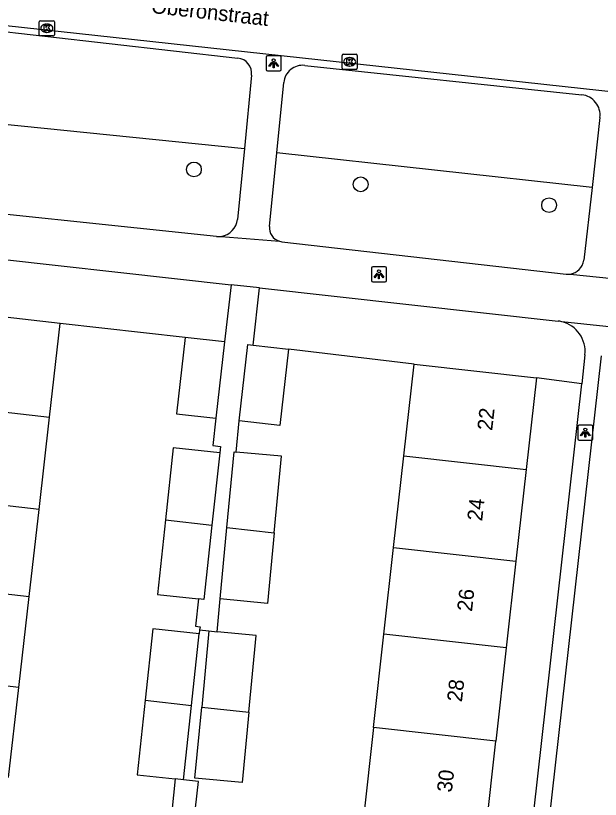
# Model space of a CAD drawing. Extents: x 161928 to 163055, y 386475 to 387428.
# Drawn here: x 162177.9 to 162216.7, y 386884.8 to 386936.8 of the extents above; entities that cross this region are included whole.
import ezdxf

# ---------------------------------------------------------------- set-up
doc = ezdxf.new("R2010")
doc.units = 0
for name, color, linetype in [('IMGEO_Boom', 7, 'Continuous'), ('IMGEO_Erf', 7, 'Continuous'), ('IMGEO_Groenvoorziening', 7, 'Continuous'), ('IMGEO_Kolk', 7, 'Continuous'), ('IMGEO_Lichtpunt', 7, 'Continuous'), ('IMGEO_Openbare_ruimte_label', 7, 'Continuous'), ('IMGEO_Pand', 7, 'Continuous'), ('IMGEO_Pand_nummerreeks', 7, 'Continuous'), ('IMGEO_Rijbaan_lokaal_open', 7, 'Continuous'), ('IMGEO_Voetpad_open', 7, 'Continuous')]:
    doc.layers.add(name, color=color, linetype=linetype)

msp = doc.modelspace()

# ---------------------------------------------------------------- linework, layer by layer
at = {"layer": 'IMGEO_Boom'}
for centre in [(162189.755, 386926.564), (162200.806, 386925.576), (162213.295, 386924.199)]:
    msp.add_circle(centre, 0.489, dxfattribs=at)
at = {"layer": 'IMGEO_Erf'}
msp.add_lwpolyline([(162190.133, 386896.057), (162190.105, 386895.794)], dxfattribs=at)
at = {"layer": 'IMGEO_Groenvoorziening'}
for points in [[(162169.363, 386930.364), (162193.098, 386927.955)], [(162216.138, 386925.375), (162195.245, 386927.667)], [(162189.178, 386915.439), (162180.893, 386916.367)], [(162204.343, 386913.676), (162196.021, 386914.657)], [(162215.453, 386912.353), (162212.452, 386912.769)]]:
    msp.add_lwpolyline(points, dxfattribs=at)
at = {"layer": 'IMGEO_Kolk'}
for p, q in [((162179.503, 386935.493), (162179.503, 386936.345)), ((162179.578, 386936.419), (162180.43, 386936.419)), ((162180.504, 386936.345), (162180.504, 386935.493)), ((162179.991, 386936.199), (162180.016, 386936.199)), ((162180.43, 386935.419), (162179.578, 386935.419)), ((162180.014, 386935.639), (162179.989, 386935.639)), ((162199.648, 386934.197), (162200.5, 386934.197)), ((162199.573, 386933.271), (162199.573, 386934.123)), ((162200.061, 386933.977), (162200.086, 386933.977)), ((162200.574, 386934.123), (162200.574, 386933.271)), ((162200.5, 386933.197), (162199.648, 386933.197)), ((162200.084, 386933.417), (162200.059, 386933.417))]:
    msp.add_line(p, q, dxfattribs=at)
for points in [[(162179.503, 386935.493), (162179.503, 386936.345)], [(162179.578, 386936.419), (162180.43, 386936.419)], [(162180.504, 386936.345), (162180.504, 386935.493)], [(162179.824, 386936.119), (162179.947, 386936.119), (162179.947, 386935.968), (162180.077, 386936.119), (162180.241, 386936.119), (162180.095, 386935.968), (162180.248, 386935.719), (162180.096, 386935.719), (162180.011, 386935.883), (162179.947, 386935.816), (162179.947, 386935.719), (162179.824, 386935.719), (162179.824, 386936.119)], [(162180.43, 386935.419), (162179.578, 386935.419)], [(162199.648, 386934.197), (162200.5, 386934.197)], [(162199.573, 386933.271), (162199.573, 386934.123)], [(162199.894, 386933.897), (162200.017, 386933.897), (162200.017, 386933.746), (162200.147, 386933.897), (162200.311, 386933.897), (162200.165, 386933.746), (162200.318, 386933.497), (162200.166, 386933.497), (162200.081, 386933.661), (162200.017, 386933.594), (162200.017, 386933.497), (162199.894, 386933.497), (162199.894, 386933.897)], [(162200.574, 386934.123), (162200.574, 386933.271)], [(162200.5, 386933.197), (162199.648, 386933.197)]]:
    msp.add_lwpolyline(points, dxfattribs=at)
for centre, start, end in [((162179.58, 386936.343), 91.552, 178.448), ((162179.58, 386936.343), 91.552, 178.448), ((162180.428, 386936.343), 1.552, 88.448), ((162180.428, 386936.343), 1.552, 88.448), ((162179.58, 386935.495), 181.552, 268.448), ((162179.58, 386935.495), 181.552, 268.448), ((162180.428, 386935.495), 271.552, 358.448), ((162180.428, 386935.495), 271.552, 358.448), ((162199.65, 386934.121), 91.552, 178.448), ((162199.65, 386934.121), 91.552, 178.448), ((162200.498, 386934.121), 1.552, 88.448), ((162200.498, 386934.121), 1.552, 88.448), ((162199.65, 386933.273), 181.552, 268.448), ((162199.65, 386933.273), 181.552, 268.448), ((162200.498, 386933.273), 271.552, 358.448), ((162200.498, 386933.273), 271.552, 358.448)]:
    msp.add_arc(centre, 0.0765, start, end, dxfattribs=at)
for centre, major_axis, ratio, start_param, end_param in [((162179.99, 386935.919), (-0.387, 0.002), 0.722429, 4.712389, 7.853982), ((162180.015, 386935.919), (-0.39, 0.002), 0.717154, 1.570796, 4.712389), ((162200.06, 386933.697), (-0.387, 0.002), 0.722429, 4.712389, 7.853982), ((162200.085, 386933.697), (-0.39, 0.002), 0.717154, 1.570796, 4.712389)]:
    msp.add_ellipse(centre, major_axis=major_axis, ratio=ratio, start_param=start_param, end_param=end_param, dxfattribs=at)
at = {"layer": 'IMGEO_Lichtpunt'}
for p, q in [((162194.538, 386934.003), (162194.538, 386933.196)), ((162194.538, 386934.003), (162194.538, 386933.196)), ((162195.44, 386934.098), (162194.632, 386934.098)), ((162195.44, 386934.098), (162194.632, 386934.098)), ((162195.534, 386933.196), (162195.534, 386934.003)), ((162195.534, 386933.196), (162195.534, 386934.003)), ((162194.632, 386933.102), (162195.44, 386933.102)), ((162194.632, 386933.102), (162195.44, 386933.102)), ((162201.518, 386920.022), (162201.518, 386919.215)), ((162201.518, 386920.022), (162201.518, 386919.215)), ((162202.42, 386920.117), (162201.612, 386920.117)), ((162202.42, 386920.117), (162201.612, 386920.117)), ((162202.514, 386919.215), (162202.514, 386920.022)), ((162202.514, 386919.215), (162202.514, 386920.022)), ((162201.612, 386919.121), (162202.42, 386919.121)), ((162201.612, 386919.121), (162202.42, 386919.121)), ((162215.195, 386909.536), (162215.195, 386908.729)), ((162215.195, 386909.536), (162215.195, 386908.729)), ((162216.097, 386909.631), (162215.289, 386909.631)), ((162216.097, 386909.631), (162215.289, 386909.631)), ((162216.191, 386908.729), (162216.191, 386909.536)), ((162216.191, 386908.729), (162216.191, 386909.536)), ((162215.289, 386908.635), (162216.097, 386908.635)), ((162215.289, 386908.635), (162216.097, 386908.635))]:
    msp.add_line(p, q, dxfattribs=at)
for points in [[(162194.912, 386933.667), (162194.951, 386933.639), (162194.763, 386933.377), (162194.725, 386933.404), (162194.912, 386933.667)], [(162195.124, 386933.639), (162195.162, 386933.666), (162195.349, 386933.404), (162195.31, 386933.376), (162195.124, 386933.639)], [(162195.014, 386933.619), (162195.061, 386933.619), (162195.061, 386933.297), (162195.014, 386933.297), (162195.014, 386933.619)], [(162201.892, 386919.686), (162201.931, 386919.658), (162201.743, 386919.396), (162201.705, 386919.423), (162201.892, 386919.686)], [(162201.994, 386919.638), (162202.041, 386919.638), (162202.041, 386919.316), (162201.994, 386919.316), (162201.994, 386919.638)], [(162202.104, 386919.658), (162202.142, 386919.685), (162202.329, 386919.423), (162202.29, 386919.395), (162202.104, 386919.658)], [(162215.569, 386909.2), (162215.608, 386909.172), (162215.42, 386908.91), (162215.382, 386908.937), (162215.569, 386909.2)], [(162215.671, 386909.152), (162215.718, 386909.152), (162215.718, 386908.83), (162215.671, 386908.83), (162215.671, 386909.152)], [(162215.781, 386909.172), (162215.819, 386909.199), (162216.006, 386908.937), (162215.967, 386908.909), (162215.781, 386909.172)]]:
    msp.add_lwpolyline(points, dxfattribs=at)
for centre in [(162195.037, 386933.801), (162202.017, 386919.82), (162215.694, 386909.334)]:
    msp.add_circle(centre, 0.0994, dxfattribs=at)
for centre, start, end in [((162194.632, 386934.003), 90, 180), ((162194.632, 386934.003), 90, 180), ((162195.44, 386934.003), 0, 90), ((162195.44, 386934.003), 0, 90), ((162194.632, 386933.196), 180, 270), ((162194.632, 386933.196), 180, 270), ((162195.44, 386933.196), 270, 0), ((162195.44, 386933.196), 270, 360), ((162201.612, 386920.022), 90, 180), ((162201.612, 386920.022), 90, 180), ((162202.42, 386920.022), 0, 90), ((162202.42, 386920.022), 0, 90), ((162201.612, 386919.215), 180, 270), ((162201.612, 386919.215), 180, 270), ((162202.42, 386919.215), 270, 0), ((162202.42, 386919.215), 270, 360), ((162215.289, 386909.536), 90, 180), ((162215.289, 386909.536), 90, 180), ((162216.097, 386909.536), 0, 90), ((162216.097, 386909.536), 0, 90), ((162215.289, 386908.729), 180, 270), ((162215.289, 386908.729), 180, 270), ((162216.097, 386908.729), 270, 0), ((162216.097, 386908.729), 270, 360)]:
    msp.add_arc(centre, 0.0946, start, end, dxfattribs=at)
at = {"layer": 'IMGEO_Pand'}
for points in [[(162180.893, 386916.367), (162172.805, 386917.288)], [(162180.185, 386910.15), (162180.893, 386916.367)], [(162189.178, 386915.439), (162188.602, 386910.383), (162191.212, 386910.086)], [(162191.787, 386915.141), (162189.178, 386915.439)], [(162191.787, 386915.141), (162191.212, 386910.086)], [(162192.752, 386909.905), (162193.328, 386914.963), (162193.675, 386914.924)], [(162196.021, 386914.657), (162195.445, 386909.599), (162192.752, 386909.905)], [(162193.675, 386914.924), (162196.021, 386914.657)], [(162203.663, 386907.586), (162204.343, 386913.676)], [(162204.343, 386913.676), (162212.452, 386912.769)], [(162212.452, 386912.769), (162211.772, 386906.681)], [(162172.097, 386911.072), (162180.185, 386910.15)], [(162179.488, 386904.034), (162180.185, 386910.15)], [(162191.46, 386907.79), (162188.384, 386908.123), (162187.868, 386903.351)], [(162191.46, 386907.79), (162190.942, 386903.001)], [(162191.941, 386902.852), (162192.417, 386907.86), (162192.556, 386907.847)], [(162195.068, 386902.503), (162195.549, 386907.562), (162192.556, 386907.847)], [(162202.986, 386901.531), (162203.663, 386907.586)], [(162203.663, 386907.586), (162211.772, 386906.681)], [(162211.772, 386906.681), (162211.096, 386900.626)], [(162179.488, 386904.034), (162171.4, 386904.956)], [(162178.833, 386898.277), (162179.488, 386904.034)], [(162187.868, 386903.351), (162187.334, 386898.414), (162190.048, 386898.12)], [(162187.868, 386903.351), (162190.942, 386903.001)], [(162190.942, 386903.001), (162190.41, 386898.081), (162190.048, 386898.12)], [(162191.491, 386898.114), (162191.941, 386902.852)], [(162195.068, 386902.503), (162194.623, 386897.816), (162191.491, 386898.114)], [(162191.941, 386902.852), (162195.068, 386902.503)], [(162202.345, 386895.789), (162202.986, 386901.531)], [(162202.986, 386901.531), (162211.096, 386900.626)], [(162211.096, 386900.626), (162210.454, 386894.884)], [(162170.745, 386899.199), (162178.833, 386898.277)], [(162178.145, 386892.243), (162178.833, 386898.277)], [(162190.105, 386895.794), (162187.029, 386896.127), (162186.518, 386891.402)], [(162189.592, 386891.052), (162190.105, 386895.794)], [(162190.747, 386895.991), (162190.268, 386890.953)], [(162190.747, 386895.991), (162191.284, 386895.94)], [(162193.395, 386890.604), (162193.879, 386895.693), (162191.284, 386895.94)], [(162201.654, 386889.599), (162202.345, 386895.789)], [(162210.454, 386894.884), (162202.345, 386895.789)], [(162210.454, 386894.884), (162209.763, 386888.694)], [(162178.145, 386892.243), (162170.057, 386893.164)], [(162177.468, 386886.293), (162178.145, 386892.243)], [(162186.518, 386891.402), (162185.984, 386886.465), (162188.521, 386886.19)], [(162186.518, 386891.402), (162189.592, 386891.052)], [(162189.06, 386886.132), (162189.592, 386891.052)], [(162193.395, 386890.604), (162192.953, 386885.948), (162189.821, 386886.245), (162190.268, 386890.953)], [(162190.268, 386890.953), (162193.395, 386890.604)], [(162201.654, 386889.599), (162200.985, 386883.612)], [(162209.763, 386888.694), (162201.654, 386889.599)], [(162209.094, 386882.707), (162209.763, 386888.694)], [(162189.06, 386886.132), (162188.521, 386886.19)]]:
    msp.add_lwpolyline(points, dxfattribs=at)
at = {"layer": 'IMGEO_Rijbaan_lokaal_open'}
for points in [[(162174.718, 386936.398), (162175.881, 386936.251), (162250, 386928.164), (162274.027, 386925.3), (162282.029, 386924.397)], [(162209.374, 386848.391), (162216.766, 386914.216)]]:
    msp.add_lwpolyline(points, dxfattribs=at)
at = {"layer": 'IMGEO_Voetpad_open'}
for points in [[(162171.327, 386936.367), (162192.665, 386933.944)], [(162197.098, 386933.456), (162215.47, 386931.51)], [(162193.58, 386932.812), (162193.098, 386927.955)], [(162195.245, 386927.667), (162195.71, 386932.332)], [(162216.667, 386930.012), (162216.138, 386925.375)], [(162193.098, 386927.955), (162192.632, 386923.254)], [(162194.76, 386922.795), (162195.245, 386927.667)], [(162216.138, 386925.375), (162215.587, 386920.549)], [(162191.249, 386922.122), (162169.767, 386924.371)], [(162191.567, 386922.131), (162195.422, 386921.812)], [(162195.588, 386921.779), (162214.433, 386919.629)], [(162173.232, 386921.042), (162192.218, 386918.931)], [(162214.679, 386919.631), (162218.354, 386919.254)], [(162192.218, 386918.931), (162191.787, 386915.141)], [(162194.106, 386918.722), (162192.218, 386918.931)], [(162193.675, 386914.924), (162194.106, 386918.722)], [(162194.106, 386918.722), (162213.884, 386916.523)], [(162218.518, 386916.012), (162214.13, 386916.48)], [(162215.669, 386914.282), (162215.453, 386912.353)], [(162208.562, 386850.925), (162215.453, 386912.353)], [(162191.212, 386910.086), (162191.015, 386908.269), (162191.506, 386908.216), (162191.46, 386907.79)], [(162192.556, 386907.847), (162192.752, 386909.905)], [(162190.048, 386898.12), (162189.851, 386896.3), (162190.156, 386896.267), (162190.133, 386896.057)], [(162191.284, 386895.94), (162191.491, 386898.114)], [(162190.133, 386896.057), (162190.747, 386895.991)], [(162187.077, 386859.828), (162190.06, 386886.024), (162189.06, 386886.132)], [(162188.521, 386886.19), (162188.287, 386884.025)]]:
    msp.add_lwpolyline(points, dxfattribs=at)
for centre, radius, start, end in [((162192.55, 386932.915), 1.035, 354.2794, 83.6181), ((162196.959, 386932.209), 1.255, 83.6327, 174.3683), ((162215.32, 386930.163), 1.355, 353.601, 83.6533), ((162191.375, 386923.38), 1.263, 278.7506, 354.2863), ((162195.683, 386922.702), 0.928, 174.2551, 253.6613), ((162191.374, 386923.326), 1.211, 264.0708, 279.1715), ((162195.697, 386922.762), 0.989, 253.8469, 263.666), ((162214.548, 386920.669), 1.046, 277.2122, 353.4154), ((162214.547, 386920.707), 1.084, 263.9518, 276.9798), ((162213.637, 386914.382), 2.155, 76.7639, 83.4062), ((162213.653, 386914.508), 2.028, 353.5924, 76.4056)]:
    msp.add_arc(centre, radius, start, end, dxfattribs=at)

# ---------------------------------------------------------------- texts
at = {"layer": 'IMGEO_Openbare_ruimte_label'}
msp.add_text('Oberonstraat', height=1, rotation=353.5713, dxfattribs=at).set_placement((162186.888, 386936.936))
at = {"layer": 'IMGEO_Pand_nummerreeks'}
for s, p in [('22', (162209.52, 386909.229)), ('24', (162208.852, 386903.239)), ('26', (162208.182, 386897.247)), ('28', (162207.513, 386891.257)), ('30', (162206.844, 386885.265))]:
    msp.add_text(s, height=1, rotation=83.6261, dxfattribs=at).set_placement(p)

doc.saveas('drawing.dxf')
